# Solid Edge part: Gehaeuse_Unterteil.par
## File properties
Username: Ferdi HM
Author: Ferdi HM
Template: Din Metric Part.par
Last saved by: Ferdi
Revision: 8
Application: Solid Edge
Genauigkeit: 0,990
Teilflächenformatvorlage: Model Default
Füllformatvorlage: Normal
Coef. of Thermal Exp: 0.0
Thermal Conductivity: 0.0
Specific Heat: 0.0
Modulus of Elasticity: 0.0
Poisson's Ratio: 0.0
Yield Stress: 0.0
Ultimate Stress: 0.0
Elongation: 0.0
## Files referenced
C:\Users\mucma\Desktop\Projektarbeit\Gehaeuse_Not-Aus.par
D:\OneDrive\Dokumente\HM\6. (Fach-) Semester\Projektarbeit - Glasboilermaschine\Gehäuse Not-Aus\Gehaeuse_Unterteil.par
Din Metric Part.par
use Not-Aus\Gehaeuse_Unterteil.par
use_Not-Aus.asm
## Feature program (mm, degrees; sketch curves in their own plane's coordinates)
sketch for "unnamed Protrusion 1" plane through (0, 0, 0) normal (0, 0, 1) x-axis (1, 0, 0)
  line (19.5, -34.5) -> (19.5, 34.5)
  line (19.5, 34.5) -> (-19.5, 34.5)
  line (-19.5, 34.5) -> (-19.5, -34.5)
  line (-19.5, -34.5) -> (19.5, -34.5)
extrude "unnamed Protrusion 1" add finite 5 along -normal
sketch for "Bohrung_1" plane through (0, 0, -5) normal (0, 0, -1) x-axis (0, -1, 0)
  hole centre (-24, -13.5) bore radius 2.4
hole "Bohrung_1" diameter 4.8 through  CounterBoreDepth = 4 mm
sketch for "unnamed Hole 1" plane through (0, 0, -5) normal (0, 0, -1) x-axis (0, -1, 0)
  hole centre (24, 13.5) bore radius 2.4
hole "unnamed Hole 1" through
sketch for "unnamed Hole 2" plane through (0, 0, -5) normal (0, 0, -1) x-axis (0, -1, 0)
  hole centre (24, -13.5) bore radius 2.4
hole "unnamed Hole 2" through
sketch for "unnamed Hole 3" plane through (0, 0, -5) normal (0, 0, -1) x-axis (0, -1, 0)
  hole centre (-24, 13.5) bore radius 2.4
hole "unnamed Hole 3" through
pattern "unnamed Pattern 1" of "Bohrung_1", "unnamed Hole 1", "unnamed Hole 2", "unnamed Hole 3"
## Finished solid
Body 1: solid body, 18 faces, 28 edges, 8 vertices.
  Faces by surface: plane 10, cylinder 8
  Edges by curve: circle 16, line 12
Bounding box of the edges (mm): 39.000 x 69.000 x 5.000, from (-19.5, -34.5, -5) to (19.5, 34.5, 0).
Cylindrical faces by radius (mm): R2.4 x4, R4 x4
Planar faces by outward normal: +x 1, +y 1, +z 1, -x 1, -y 1, -z 5
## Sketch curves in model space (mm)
line (19.5, -34.5, 0) -> (19.5, 34.5, 0)
line (19.5, 34.5, 0) -> (-19.5, 34.5, 0)
line (-19.5, 34.5, 0) -> (-19.5, -34.5, 0)
line (-19.5, -34.5, 0) -> (19.5, -34.5, 0)
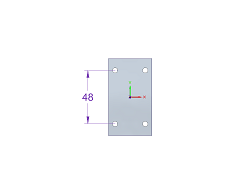
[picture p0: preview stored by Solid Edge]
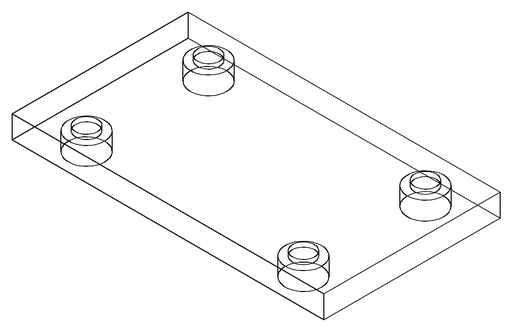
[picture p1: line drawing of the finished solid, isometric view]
